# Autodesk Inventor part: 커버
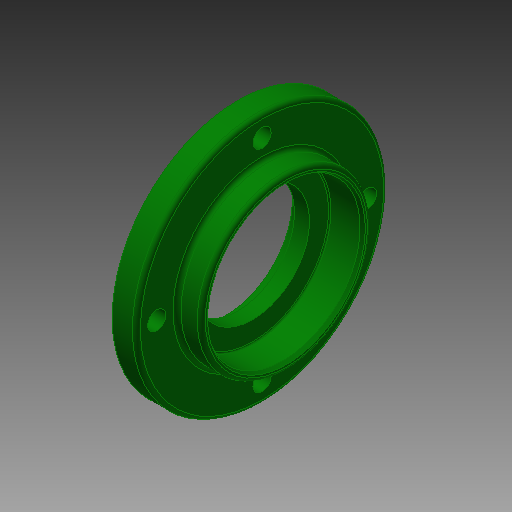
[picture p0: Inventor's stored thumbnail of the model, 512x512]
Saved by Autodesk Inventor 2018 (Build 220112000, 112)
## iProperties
Created: 2018-11
Part Number: 커버
Material: 알루미늄 6061
Document SubType Name: Modeling
Designer: mduedu
Density: 1 g/cm^3
Appearance: 진녹색
Author: mduedu
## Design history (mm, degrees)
sketch "스케치1"
  geometry: L1 (0, 0)-(3, 0); L2 (3, 0)-(3, 20); L3 (3, 20)-(0, 20); L4 (0, 20)-(0, 0); L5 (3, 0)-(9, 0); L6 (9, 0)-(9, 31); L7 (9, 31)-(3, 31); L8 (3, 31)-(3, 0); L9 (9, 0)-(15, 0); L10 (15, 0)-(15, 21); L11 (15, 21)-(9, 21); L12 (9, 21)-(9, 0)
  constraints: 24 end point, 6 parallel, 3 horizontal, 3 perpendicular
  dimensions: "d0" = 62 diameter of L7 L5; "d2" = 42 diameter of L11 L9; "d3" = 40 diameter of L3 L1; "d4" = 3 distance of L2.end L3.end; "d5" = 6 distance of L6.end L7.end; "d6" = 15 distance between parallel lines of L10 L4
revolve "회전1" sketch "스케치1" stored, may be unused: angle "d7" = 90 deg
sketch "스케치2"
  geometry: L1 (0, -20)-(0, 20) reference; L2 (0, 20)-(3, 20) reference; L3 (3, 20)-(3, 31) reference; L4 (3, 31)-(9, 31) reference; L5 (9, 31)-(9, 21) reference; L6 (9, 21)-(15, 21) reference; L7 (15, 21)-(15, -21) reference; L8 (15, -21)-(9, -21) reference; L9 (9, -21)-(9, -31) reference; L10 (9, -31)-(3, -31) reference; L11 (3, -31)-(3, -20) reference; L12 (3, -20)-(0, -20) reference; L13 (0, 0)-(3, 0); L14 (3, 0)-(3, 16.5); L15 (3, 16.5)-(0, 16.5); L16 (0, 16.5)-(0, 0); L17 (3, 0)-(6.7, 0); L18 (6.7, 0)-(6.7, 14); L19 (6.7, 14)-(3, 14); L20 (3, 14)-(3, 0); L21 (6.7, 0)-(15, 0); L22 (15, 0)-(15, 19); L23 (15, 19)-(6.7, 19); L24 (6.7, 19)-(6.7, 0)
  constraints: 24 end point, 6 parallel, 3 horizontal, 3 perpendicular, 1 point on line
  dimensions: "d8" = 38 diameter of L23 L21; "d10" = 28 diameter of L19 L17; "d11" = 33 diameter of L15 L13; "d12" = 3 distance of L14.end L15.end; "d13" = 8.3 distance of L22.end L23.end
revolve "회전2" sketch "스케치2" stored, may be unused: angle "d14" = 90 deg
fillet "모깎기1" dims "d15" = 0.3
chamfer "모따기1" distance "d16" = 0.8; stored, may be unused: second distance "d17" = 2, angle "d18" = 30 deg
fillet "모깎기2" dims "d19" = 1
chamfer "모따기2" distance "d20" = 0.5; stored, may be unused: second distance "d21" = 2, angle "d22" = 30 deg
sketch "스케치3" dims "d23" = 52
  geometry: 6 further points
  constraints: 2 vertical alignment, 1 coincident, 7 other
  dimensions: "d26" = 360 deg dimension on point (0, 0) point (0, 26) (derived)
sketch "스케치4"
  geometry: 4 further points
  constraints: 4 other
hole "구멍1" sketch "스케치4" at (-26, 0), (0, -26), (26, 0), (0, 26) diameter "d28" = 4.5; stored, may be unused: countersink angle "d32" = 90 deg, drill point angle "d34" = 0 deg; dims "d29" = 6, "d30" = 8, "d31" = 4.6, "d33" = 8
node "솔리드1"
node "절단 모서리 투영1"
